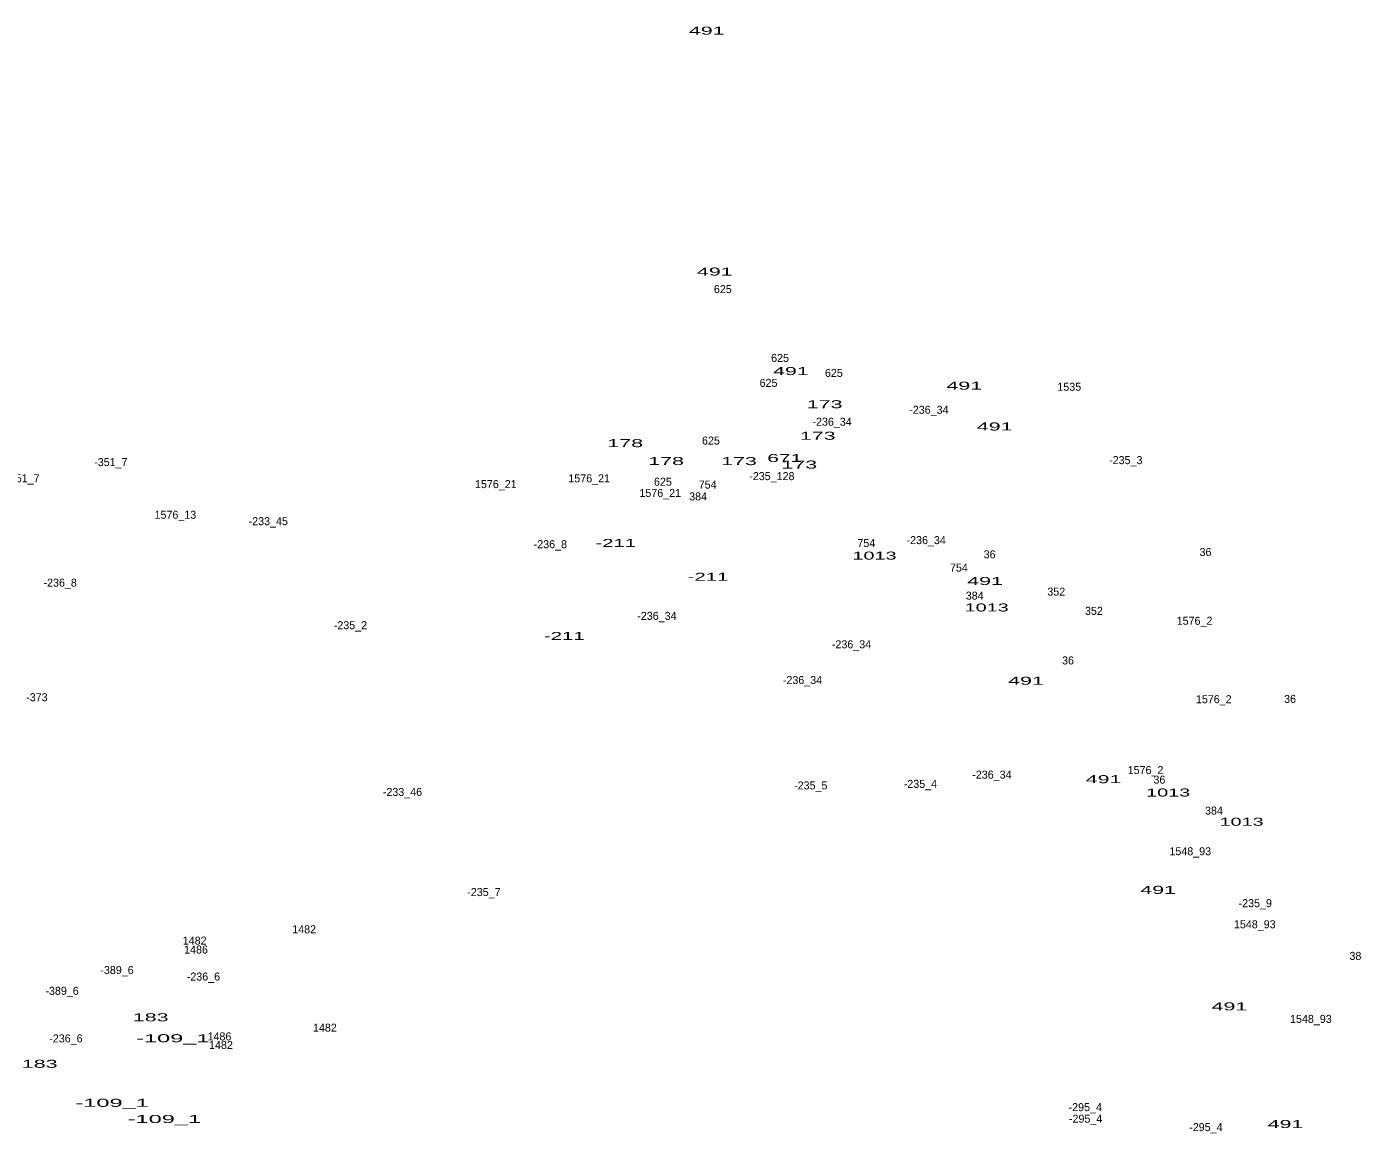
# Model space of a CAD drawing. Extents: x -660434 to -656144, y -997850 to -994016.
# Drawn here: x -658353 to -657690, y -995528 to -994975 of the extents above; entities that cross this region are included whole.
import ezdxf
from ezdxf.enums import TextEntityAlignment as Align

# ---------------------------------------------------------------- set-up
doc = ezdxf.new("R2010")
doc.units = 0
doc.header["$LTSCALE"] = 1.6
doc.layers.add('24', color=7, linetype='Continuous')

msp = doc.modelspace()

# ---------------------------------------------------------------- texts
at = {"layer": '24'}
for s, width, p in [('491', 2, (-658013.068, -994978.87)), ('491', 2, (-658009.038, -995099.23)), ('491', 2, (-657971.018, -995148.95)), ('491', 2, (-657884.348, -995156.25)), ('173', 2, (-657954.133, -995165.51)), ('173', 2, (-657957.593, -995181.26)), ('491', 2, (-657869.178, -995176.63)), ('178', 2, (-658053.813, -995184.95)), ('178', 2, (-658033.363, -995193.88)), ('173', 2, (-657996.953, -995193.93)), ('671', 1.95, (-657974.097, -995192.39)), ('173', 2, (-657966.803, -995195.66)), ('-211', 1.9, (-658058.547, -995234.82)), ('1013', 1.85, (-657929.23, -995241.14)), ('-211', 1.9, (-658012.457, -995251.72)), ('491', 2, (-657873.978, -995253.84)), ('1013', 1.85, (-657873.16, -995267.07)), ('-211', 1.9, (-658084.267, -995281.3)), ('491', 2, (-657853.508, -995303.66)), ('491', 2, (-657814.728, -995352.84)), ('1013', 1.85, (-657782.44, -995359.51)), ('1013', 1.85, (-657745.76, -995374.11)), ('491', 2, (-657787.458, -995408.15)), ('491', 2, (-657751.838, -995466.37)), ('183', 2, (-658290.987, -995471.81)), ('-109_1', 2.2, (-658279.939, -995482.28)), ('183', 2, (-658346.477, -995495.05)), ('-109_1', 2.2, (-658310.279, -995514.55)), ('-109_1', 2.2, (-658284.159, -995522.62)), ('491', 2, (-657723.808, -995525.15))]:
    msp.add_text(s, height=4, dxfattribs=dict(at, width=width)).set_placement(p, align=Align.CENTER)
for s, p in [('625', (-658005.033, -995107.99)), ('625', (-657976.423, -995142.37)), ('625', (-657949.543, -995149.86)), ('625', (-657982.183, -995154.85)), ('1535', (-657831.87, -995156.78)), ('-236_34', (-657902.041, -995168.29)), ('-236_34', (-657950.431, -995174.25)), ('625', (-658010.983, -995183.66)), ('-351_7', (-658310.902, -995194.42)), ('-235_3', (-657803.622, -995193.44)), ('-351_7', (-658354.872, -995202.49)), ('1576_21', (-658071.833, -995202.54)), ('-235_128', (-657980.515, -995201.43)), ('1576_21', (-658118.493, -995205.42)), ('625', (-658034.983, -995204.22)), ('754', (-658012.617, -995205.66)), ('1576_21', (-658036.313, -995209.84)), ('384', (-658017.391, -995211.57)), ('1576_13', (-658278.663, -995220.74)), ('-233_45', (-658232.226, -995223.95)), ('-236_8', (-658091.248, -995235.45)), ('754', (-657933.317, -995234.85)), ('-236_34', (-657903.391, -995233.41)), ('36', (-657871.683, -995240.52)), ('36', (-657763.773, -995239.36)), ('754', (-657887.047, -995247.14)), ('-236_8', (-658336.248, -995254.66)), ('384', (-657879.141, -995261.13)), ('352', (-657838.377, -995259.14)), ('352', (-657819.557, -995268.74)), ('-235_2', (-658191.152, -995275.92)), ('-236_34', (-658037.981, -995271.25)), ('1576_2', (-657769.26, -995273.7)), ('-236_34', (-657940.711, -995285.46)), ('36', (-657832.513, -995293.53)), ('-236_34', (-657965.211, -995303.32)), ('-373', (-658347.861, -995311.91)), ('1576_2', (-657759.66, -995312.88)), ('36', (-657721.533, -995312.74)), ('1576_2', (-657793.75, -995348.29)), ('-235_4', (-657906.277, -995355.19)), ('-236_34', (-657870.551, -995350.57)), ('36', (-657786.823, -995353.07)), ('-233_46', (-658165.141, -995359.22)), ('-235_5', (-657961.092, -995355.96)), ('384', (-657759.561, -995368.54)), ('1548_93', (-657771.407, -995388.86)), ('-235_7', (-658124.438, -995409.25)), ('-235_9', (-657738.928, -995414.8)), ('1482', (-658214.294, -995427.84)), ('1548_93', (-657739.157, -995425.35)), ('1482', (-658269.024, -995433.51)), ('1486', (-658268.34, -995437.97)), ('384', (-657687.371, -995441.14)), ('-389_6', (-658307.823, -995448.22)), ('-236_6', (-658264.623, -995451.45)), ('-389_6', (-658335.283, -995458.59)), ('1548_93', (-657711.117, -995472.61)), ('1486', (-658256.62, -995481.38)), ('1482', (-658203.924, -995477.01)), ('-236_6', (-658333.363, -995482.37)), ('1482', (-658255.864, -995485.66)), ('-295_4', (-657823.892, -995516.71)), ('-295_4', (-657823.702, -995522.47)), ('-295_4', (-657763.602, -995526.7))]:
    msp.add_text(s, height=4, dxfattribs=at).set_placement(p, align=Align.CENTER)

doc.saveas('drawing.dxf')
